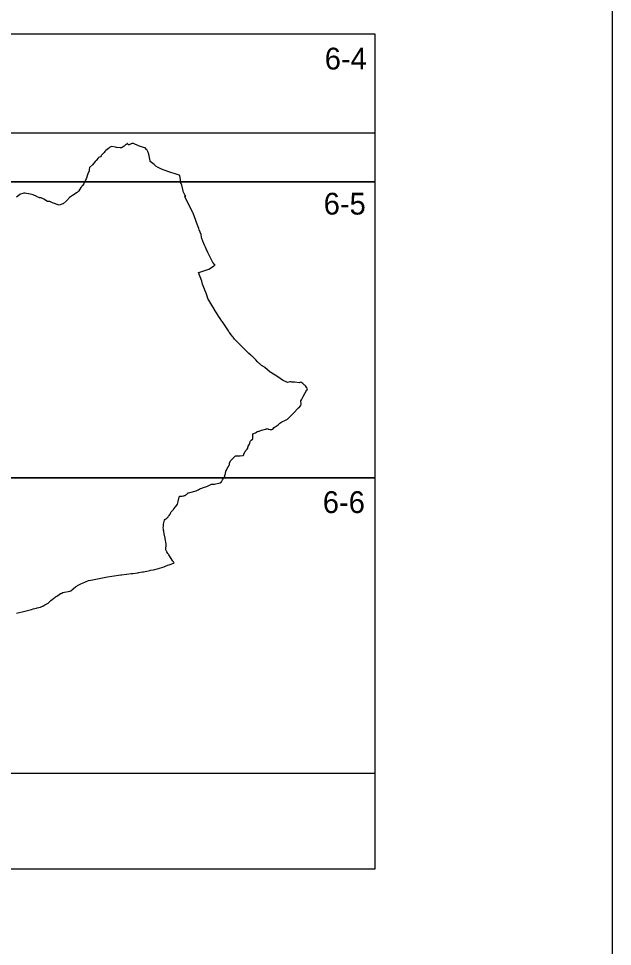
# Model space of a CAD drawing. Extents: x -449577 to -425530, y -1150048 to -1121091.
# Drawn here: x -433224 to -432973.1, y -1126663.9 to -1126271.9 of the extents above; entities that cross this region are included whole.
import ezdxf

# ---------------------------------------------------------------- set-up
doc = ezdxf.new("R2010")
doc.units = 0
for name, color, linetype in [('Vrstva 1', 7, 'Continuous'), ('Vrstva 10', 7, 'Continuous'), ('Vrstva 4', 7, 'Continuous')]:
    doc.layers.add(name, color=color, linetype=linetype)

msp = doc.modelspace()

# ---------------------------------------------------------------- linework, layer by layer
at = {"layer": 'Vrstva 1'}
msp.add_lwpolyline([(-434458.08, -1126016.81), (-434458.08, -1127066.81), (-432973.08, -1127066.81), (-432973.08, -1126016.81)], close=True, dxfattribs=at)
msp.add_lwpolyline([(-433224.79, -1126523.09), (-433221.25, -1126522.22), (-433218.48, -1126521.55), (-433217.81, -1126521.34), (-433216.32, -1126520.98), (-433216.11, -1126520.92), (-433214.68, -1126520.53), (-433214.08, -1126520.27), (-433213.86, -1126520.17), (-433213.7, -1126520.11), (-433212.88, -1126519.66), (-433212.82, -1126519.62), (-433211.51, -1126518.84), (-433210.36, -1126517.79), (-433209.71, -1126517.29), (-433209.58, -1126517.18), (-433209.56, -1126517.17), (-433209.4, -1126517.04), (-433209.25, -1126516.94), (-433208.45, -1126516.38), (-433208.39, -1126516.34), (-433208.32, -1126516.29), (-433207.81, -1126515.94), (-433207.44, -1126515.68), (-433206.78, -1126515.22), (-433206.19, -1126514.81), (-433206.03, -1126514.84), (-433206.02, -1126514.84), (-433206, -1126514.82), (-433205.27, -1126514.43), (-433202.31, -1126513.85), (-433201.89, -1126513.7), (-433199.86, -1126512.07), (-433199.39, -1126511.73), (-433199.36, -1126511.71), (-433199, -1126511.45), (-433198.82, -1126511.33), (-433197.43, -1126510.63), (-433196.02, -1126509.99), (-433195.72, -1126509.84), (-433194.46, -1126509.38), (-433193.46, -1126509.13), (-433187.75, -1126508.07), (-433186.33, -1126507.81), (-433184.62, -1126507.56), (-433180.75, -1126506.99), (-433180.51, -1126506.96), (-433176.21, -1126506.44), (-433175.68, -1126506.38), (-433173.53, -1126506.02), (-433173.21, -1126505.97), (-433171.55, -1126505.7), (-433171.15, -1126505.63), (-433169.74, -1126505.34), (-433168.45, -1126505.07), (-433168.24, -1126505.03), (-433167.07, -1126504.8), (-433166.4, -1126504.67), (-433166.38, -1126504.67), (-433165.47, -1126504.46), (-433165.4, -1126504.44), (-433164.75, -1126504.28), (-433164.4, -1126504.17), (-433163.51, -1126503.88), (-433163.07, -1126503.73), (-433162.42, -1126503.49), (-433162.3, -1126503.45), (-433161.21, -1126502.96), (-433161.21, -1126502.96), (-433161.09, -1126502.92), (-433160.44, -1126502.69), (-433160.35, -1126502.66), (-433159.92, -1126502.5), (-433158.26, -1126501.92), (-433158.28, -1126501.87), (-433158.39, -1126501.7), (-433158.55, -1126501.47), (-433158.77, -1126501.15), (-433160.47, -1126498.51), (-433160.68, -1126498.16), (-433160.85, -1126497.89), (-433161.29, -1126497.18), (-433161.82, -1126496.33), (-433161.66, -1126493.97), (-433161.65, -1126493.88), (-433162.04, -1126491.58), (-433162.04, -1126491.56), (-433162.05, -1126491.54), (-433162.05, -1126491.54), (-433162.05, -1126491.51), (-433162.46, -1126489.68), (-433162.47, -1126489.49), (-433162.53, -1126488.69), (-433162.63, -1126488.41), (-433162.64, -1126488.39), (-433162.75, -1126488.17), (-433162.79, -1126488.09), (-433162.8, -1126487.71), (-433162.83, -1126487.01), (-433162.78, -1126486.52), (-433162.78, -1126486.5), (-433162.69, -1126485.64), (-433162.67, -1126485.53), (-433162.38, -1126483.89), (-433162.3, -1126483.81), (-433162, -1126483.47), (-433161.94, -1126483.4), (-433161.68, -1126483.28), (-433161.62, -1126483.22), (-433161.36, -1126483.02), (-433161.13, -1126482.84), (-433160.92, -1126482.68), (-433160.86, -1126482.64), (-433160.78, -1126482.51), (-433160.7, -1126482.39), (-433160.59, -1126482.22), (-433160.37, -1126481.89), (-433159.95, -1126481.24), (-433159.82, -1126480.99), (-433159.81, -1126480.98), (-433159.67, -1126480.69), (-433159.62, -1126480.6), (-433159.44, -1126480.27), (-433159.3, -1126480.12), (-433159, -1126479.81), (-433158.83, -1126479.63), (-433158.55, -1126479.28), (-433158.42, -1126479.11), (-433157.73, -1126478.26), (-433157.07, -1126477.45), (-433156.78, -1126477.09), (-433156.54, -1126475.92), (-433156.48, -1126475.69), (-433156.41, -1126475.41), (-433156.09, -1126474.1), (-433156.01, -1126473.82), (-433156.01, -1126473.79), (-433155.99, -1126473.74), (-433155.83, -1126473.73), (-433155.81, -1126473.73), (-433155.57, -1126473.73), (-433154.88, -1126473.71), (-433154.87, -1126473.71), (-433154.84, -1126473.71), (-433154.16, -1126473.53), (-433153.96, -1126473.47), (-433153.54, -1126473.36), (-433153.52, -1126473.35), (-433153.46, -1126473.29), (-433153.16, -1126473.01), (-433153.04, -1126472.93), (-433152.7, -1126472.67), (-433152.28, -1126472.35), (-433152.21, -1126472.33), (-433151.65, -1126472.17), (-433148.95, -1126471.41), (-433148.36, -1126471.14), (-433148.03, -1126470.98), (-433147.98, -1126470.96), (-433147.88, -1126470.91), (-433147.52, -1126470.73), (-433147.47, -1126470.71), (-433147.44, -1126470.69), (-433147.43, -1126470.69), (-433147.4, -1126470.67), (-433147.09, -1126470.52), (-433147.03, -1126470.48), (-433146.92, -1126470.43), (-433145.84, -1126470.1), (-433145.41, -1126469.92), (-433144.89, -1126469.7), (-433143.88, -1126469.29), (-433142.46, -1126468.66), (-433142.32, -1126468.65), (-433141.19, -1126468.6), (-433138.79, -1126468.04), (-433138.26, -1126467.64), (-433138.19, -1126467.52), (-433138.1, -1126467.34), (-433137.84, -1126466.83), (-433137.49, -1126466.4), (-433137.47, -1126466.37), (-433137.26, -1126466.08), (-433137.15, -1126465.92), (-433137.14, -1126465.91), (-433136.6, -1126464.13), (-433136.59, -1126464.1), (-433136.39, -1126463.15), (-433136.13, -1126462.69), (-433135.94, -1126462.36), (-433135.39, -1126461.24), (-433135.01, -1126460.73), (-433134.98, -1126460.6), (-433134.91, -1126460.3), (-433134.88, -1126460.16), (-433134.82, -1126459.91), (-433134.8, -1126459.81), (-433134.48, -1126458.8), (-433134.47, -1126458.79), (-433134.18, -1126458.51), (-433133.52, -1126457.88), (-433133.47, -1126457.83), (-433133, -1126457.35), (-433132.74, -1126457.09), (-433132.64, -1126456.98), (-433132.27, -1126456.66), (-433132.23, -1126456.66), (-433132.22, -1126456.66), (-433131.81, -1126456.65), (-433131.64, -1126456.66), (-433131.01, -1126456.68), (-433130.3, -1126456.68), (-433129.33, -1126456.59), (-433129.3, -1126456.59), (-433129.05, -1126456.56), (-433128.83, -1126456.2), (-433128.78, -1126456.07), (-433128.76, -1126456.02), (-433128.74, -1126455.96), (-433128.38, -1126454.94), (-433128.24, -1126454.77), (-433128.14, -1126454.66), (-433128.1, -1126454.62), (-433128.04, -1126454.54), (-433127.92, -1126454.41), (-433127.65, -1126454.09), (-433127.56, -1126453.99), (-433127.46, -1126453.87), (-433127.12, -1126453.48), (-433127.05, -1126453.09), (-433126.99, -1126452.78), (-433126.92, -1126452.65), (-433126.37, -1126451.73), (-433126.26, -1126451.34), (-433126.07, -1126450.64), (-433125.95, -1126450.35), (-433125.66, -1126450.08), (-433125.11, -1126449.57), (-433125.04, -1126449.51), (-433124.94, -1126447.4), (-433123.92, -1126446.91), (-433123.52, -1126446.7), (-433123.27, -1126446.57), (-433122.98, -1126446.41), (-433122.76, -1126446.33), (-433122.42, -1126446.2), (-433122.37, -1126446.19), (-433121.28, -1126445.78), (-433121.27, -1126445.78), (-433120.78, -1126445.72), (-433120.7, -1126445.7), (-433119.67, -1126445.44), (-433119.52, -1126445.4), (-433119.43, -1126445.37), (-433119.26, -1126445.32), (-433118.73, -1126445.15), (-433118.73, -1126445.15), (-433118.72, -1126445.16), (-433118.72, -1126445.16), (-433118.69, -1126445.22), (-433118.56, -1126445.44), (-433117.68, -1126445.54), (-433117.48, -1126445.56), (-433117.12, -1126445.6), (-433117.03, -1126445.56), (-433116.6, -1126445.38), (-433115.95, -1126444.67), (-433114.31, -1126443.51), (-433114.22, -1126443.44), (-433114.05, -1126443.33), (-433113.54, -1126442.91), (-433112.79, -1126442.31), (-433111.52, -1126441.74), (-433110.9, -1126441.47), (-433110.36, -1126441.23), (-433110.3, -1126441.2), (-433108.65, -1126439.53), (-433107.81, -1126438.64), (-433107.45, -1126438.26), (-433106.26, -1126436.9), (-433105.66, -1126436.44), (-433105.61, -1126436.4), (-433104.77, -1126435.39), (-433104.57, -1126434.82), (-433104.66, -1126433.49), (-433104.44, -1126433), (-433103.8, -1126431.55), (-433102.34, -1126429.07), (-433102.31, -1126429.02), (-433102.31, -1126429.02), (-433102.29, -1126428.99), (-433102.26, -1126428.95), (-433102.11, -1126428.76), (-433101.85, -1126428.42), (-433102.11, -1126428.12), (-433102.25, -1126427.9), (-433102.72, -1126427.16), (-433102.92, -1126426.97), (-433103.07, -1126426.81), (-433103.26, -1126426.61), (-433103.84, -1126426.04), (-433104.69, -1126425.57), (-433105.14, -1126425.75), (-433105.47, -1126425.87), (-433107.22, -1126425.6), (-433107.83, -1126425.51), (-433107.97, -1126425.5), (-433108.56, -1126425.48), (-433108.94, -1126425.43), (-433109.1, -1126425.4), (-433109.14, -1126425.4), (-433109.17, -1126425.39), (-433109.17, -1126425.39), (-433109.2, -1126425.4), (-433109.3, -1126425.43), (-433109.43, -1126425.46), (-433110.33, -1126425.7), (-433110.4, -1126425.67), (-433112.47, -1126424.63), (-433114.49, -1126423.35), (-433117.4, -1126421.53), (-433117.56, -1126421.39), (-433117.6, -1126421.36), (-433117.69, -1126421.28), (-433118.83, -1126420.35), (-433119.98, -1126419.3), (-433120.09, -1126419.2), (-433121.3, -1126418.44), (-433121.58, -1126418.21), (-433122.21, -1126417.71), (-433122.52, -1126417.47), (-433123.02, -1126416.94), (-433123.74, -1126416.18), (-433123.89, -1126416.02), (-433124.35, -1126415.53), (-433125.32, -1126414.5), (-433125.52, -1126414.39), (-433125.52, -1126414.39), (-433125.7, -1126414.3), (-433125.9, -1126414.2), (-433126.73, -1126413.37), (-433127.36, -1126412.74), (-433128.54, -1126411.57), (-433129.47, -1126410.63), (-433129.63, -1126410.48), (-433130.07, -1126410.03), (-433130.31, -1126409.79), (-433130.4, -1126409.7), (-433130.44, -1126409.66), (-433130.96, -1126409.14), (-433131.6, -1126408.49), (-433131.68, -1126408.41), (-433131.7, -1126408.39), (-433131.85, -1126408.24), (-433132.68, -1126407.4), (-433133.06, -1126406.9), (-433133.34, -1126406.53), (-433133.66, -1126406.1), (-433134.02, -1126405.62), (-433134.97, -1126404.36), (-433135.34, -1126403.82), (-433137.88, -1126400.08), (-433138.05, -1126399.82), (-433138.82, -1126398.63), (-433139.49, -1126397.62), (-433140.33, -1126396.29), (-433141.13, -1126395.02), (-433141.21, -1126394.89), (-433142.3, -1126393.04), (-433143.98, -1126390.19), (-433143.98, -1126390.18), (-433143.98, -1126390.18), (-433143.99, -1126390.18), (-433144.32, -1126389.2), (-433144.77, -1126387.9), (-433144.83, -1126387.7), (-433146.21, -1126384.19), (-433146.5, -1126382.94), (-433147.98, -1126379.26), (-433147.35, -1126379.06), (-433143.63, -1126377.82), (-433141.66, -1126376.6), (-433141.48, -1126376.49), (-433141.42, -1126376.45), (-433141.22, -1126376.33), (-433140.95, -1126376.16), (-433141.87, -1126374.97), (-433143.28, -1126372.19), (-433144.03, -1126370.72), (-433144.56, -1126369.56), (-433144.58, -1126369.52), (-433144.64, -1126369.39), (-433144.65, -1126369.36), (-433144.67, -1126369.33), (-433144.71, -1126369.24), (-433145.04, -1126368.51), (-433145.36, -1126367.72), (-433146.07, -1126365.95), (-433146.48, -1126364.91), (-433146.63, -1126364.28), (-433146.89, -1126363.15), (-433147.63, -1126361.26), (-433147.83, -1126360.66), (-433148.77, -1126358.03), (-433149.04, -1126357.31), (-433150.23, -1126354.22), (-433150.3, -1126354.04), (-433150.33, -1126353.96), (-433153.68, -1126347.15), (-433153.37, -1126347.01), (-433153.35, -1126347), (-433153.45, -1126346.83), (-433153.53, -1126346.73), (-433153.7, -1126346.5), (-433153.76, -1126346.42), (-433154.37, -1126344.94), (-433154.42, -1126344.65), (-433154.52, -1126344.19), (-433154.53, -1126344.13), (-433155.04, -1126342.29), (-433155.34, -1126341.66), (-433155.35, -1126341.58), (-433155.39, -1126341.22), (-433155.53, -1126340.13), (-433155.81, -1126338.29), (-433155.87, -1126338.27), (-433156.17, -1126338.17), (-433156.55, -1126337.91), (-433156.56, -1126337.91), (-433160.86, -1126336.5), (-433163.65, -1126335.52), (-433164.96, -1126334.9), (-433165.93, -1126334.34), (-433166.65, -1126333.56), (-433168.33, -1126332.29), (-433168.39, -1126331.99), (-433168.97, -1126329.29), (-433169.12, -1126328.75), (-433169.3, -1126328.24), (-433169.35, -1126328.08), (-433169.6, -1126327.56), (-433169.85, -1126327.25), (-433170.43, -1126326.56), (-433171.18, -1126326.35), (-433173.36, -1126325.69), (-433175.45, -1126324.73), (-433176.07, -1126324.73), (-433177.02, -1126325.1), (-433177.15, -1126325.19), (-433177.22, -1126325.24), (-433177.36, -1126325.34), (-433177.4, -1126325.37), (-433177.42, -1126325.35), (-433177.63, -1126325.1), (-433177.88, -1126324.82), (-433177.96, -1126324.72), (-433178.05, -1126324.76), (-433178.56, -1126325.15), (-433178.75, -1126325.3), (-433179.42, -1126325.82), (-433180.17, -1126326.38), (-433180.51, -1126326.6), (-433181.1, -1126326.56), (-433182.58, -1126326.41), (-433183.04, -1126326.32), (-433184.63, -1126326), (-433184.93, -1126326.11), (-433185.49, -1126326.46), (-433186.04, -1126326.78), (-433186.53, -1126327.24), (-433187.06, -1126327.73), (-433187.46, -1126328.12), (-433187.47, -1126328.13), (-433187.8, -1126328.47), (-433187.93, -1126328.61), (-433188.44, -1126329.16), (-433188.89, -1126329.71), (-433189.05, -1126329.9), (-433189.41, -1126330.33), (-433190.15, -1126330.66), (-433190.17, -1126330.66), (-433190.37, -1126330.91), (-433191.23, -1126331.93), (-433191.61, -1126332.38), (-433192.74, -1126333.74), (-433192.75, -1126333.75), (-433193.99, -1126334.92), (-433194.11, -1126335.76), (-433194.16, -1126336.13), (-433194.2, -1126336.23), (-433194.68, -1126337.58), (-433195.12, -1126338.82), (-433195.15, -1126338.9), (-433195.45, -1126339.59), (-433196.38, -1126341.77), (-433196.4, -1126341.78), (-433196.97, -1126342.46), (-433197.27, -1126342.81), (-433197.27, -1126342.82), (-433197.61, -1126343.36), (-433198.48, -1126344.75), (-433198.57, -1126344.89), (-433198.74, -1126345.02), (-433199.27, -1126345.41), (-433199.88, -1126345.86), (-433199.88, -1126345.86), (-433200.85, -1126346.49), (-433200.98, -1126346.58), (-433201.16, -1126346.7), (-433202.46, -1126347.56), (-433202.47, -1126347.57), (-433202.73, -1126347.83), (-433202.85, -1126347.95), (-433203.07, -1126348.18), (-433203.35, -1126348.46), (-433203.92, -1126349.03), (-433205.08, -1126350.19), (-433205.28, -1126350.27), (-433206.78, -1126350.84), (-433209.59, -1126349.72), (-433209.59, -1126349.73), (-433209.6, -1126349.75), (-433210.51, -1126349.37), (-433210.82, -1126349.24), (-433210.84, -1126349.24), (-433211.23, -1126349.24), (-433211.71, -1126349.24), (-433213.27, -1126348.25), (-433213.53, -1126348.12), (-433213.82, -1126347.96), (-433213.88, -1126347.93), (-433213.92, -1126347.91), (-433214.46, -1126347.68), (-433214.51, -1126347.68), (-433214.52, -1126347.68), (-433214.67, -1126347.67), (-433214.79, -1126347.66), (-433215.1, -1126347.64), (-433215.12, -1126347.64), (-433215.12, -1126347.64), (-433215.23, -1126347.6), (-433215.47, -1126347.5), (-433216.07, -1126347.25), (-433216.23, -1126347.18), (-433217.75, -1126346.45), (-433218.37, -1126346.27), (-433219.04, -1126346.07), (-433221.36, -1126345.64), (-433221.37, -1126345.64), (-433221.77, -1126345.75), (-433223.51, -1126346.33), (-433223.64, -1126346.44), (-433224.85, -1126347.4)], dxfattribs=at)
at = {"layer": 'Vrstva 10'}
msp.add_lwpolyline([(-433073.49, -1126320.23), (-433073.49, -1126631.21), (-433406.36, -1126631.21), (-433406.36, -1126465.91), (-433385.99, -1126465.91), (-433385.99, -1126340.91), (-433385.99, -1126320.23), (-433073.49, -1126320.23)], dxfattribs=at)
at = {"layer": 'Vrstva 4'}
msp.add_line((-433385.99, -1126278.41), (-433073.49, -1126278.41), dxfattribs=at)
msp.add_lwpolyline([(-433073.49, -1126278.41), (-433073.49, -1126340.91), (-433229.74, -1126340.91), (-433229.74, -1126278.41)], dxfattribs=at)
for points in [[(-433073.49, -1126340.91), (-433073.49, -1126465.91), (-433229.74, -1126465.91), (-433229.74, -1126340.91)], [(-433073.49, -1126465.91), (-433073.49, -1126590.91), (-433229.74, -1126590.91), (-433229.74, -1126465.91)]]:
    msp.add_lwpolyline(points, close=True, dxfattribs=at)

# ---------------------------------------------------------------- texts
at = {"layer": 'Vrstva 1'}
for s, p in [('6-4', (-433094.62, -1126293.46)), ('6-5', (-433095.07, -1126354.75)), ('6-6', (-433095.44, -1126480.82))]:
    msp.add_text(s, height=9.2, dxfattribs=at).set_placement(p)

doc.saveas('drawing.dxf')
